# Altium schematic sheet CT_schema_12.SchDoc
size 389 x 385 mm
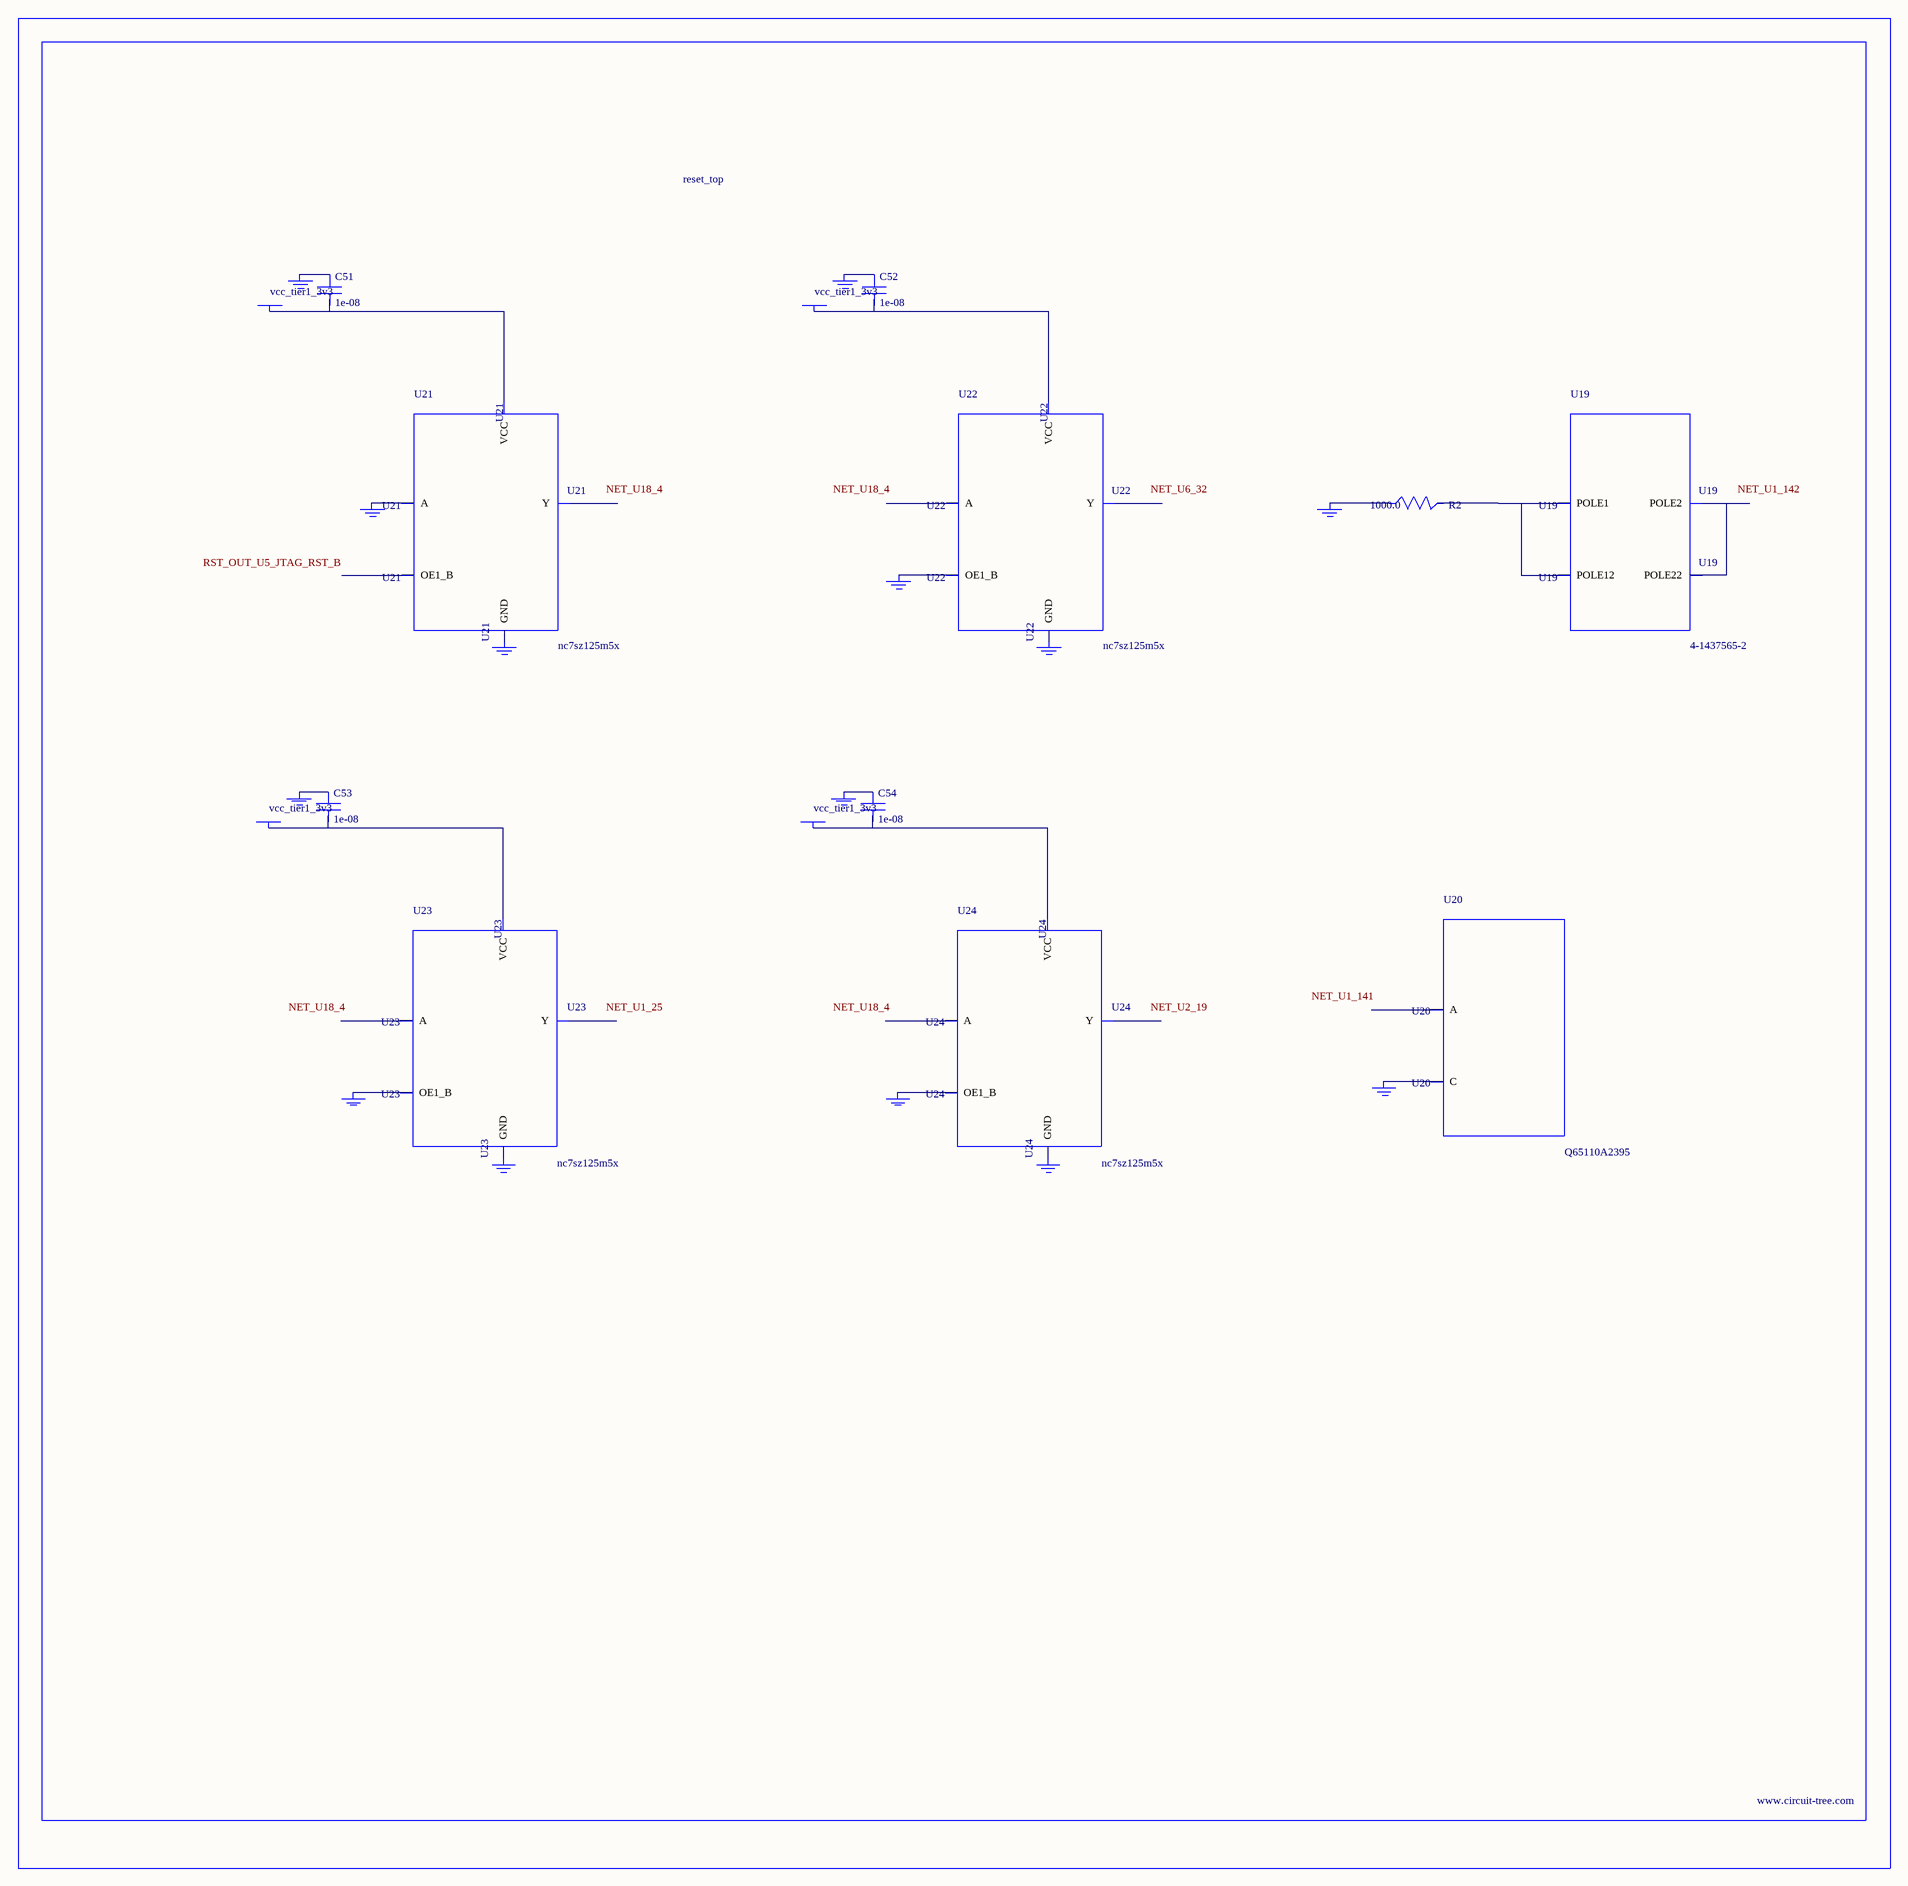
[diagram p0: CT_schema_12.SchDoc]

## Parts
BORDER11  (no value)
C51  1e-08  [C0402]
C52  1e-08  [C0402]
C53  1e-08  [C0402]
C54  1e-08  [C0402]
GND_INSTANCE_11_0  (no value)
GND_INSTANCE_11_1  (no value)
GND_INSTANCE_11_2  (no value)
GND_INSTANCE_11_3  (no value)
GND_INSTANCE_11_4  (no value)
GND_INSTANCE_11_5  (no value)
GND_INSTANCE_11_6  (no value)
GND_INSTANCE_11_7  (no value)
GND_INSTANCE_11_8  (no value)
GND_INSTANCE_11_9  (no value)
GND_INSTANCE_11_10  (no value)
GND_INSTANCE_11_11  (no value)
GND_INSTANCE_11_12  (no value)
GND_INSTANCE_11_13  (no value)
POWER_INSTANCE_11_0  vcc_tier1_3v3
POWER_INSTANCE_11_1  vcc_tier1_3v3
POWER_INSTANCE_11_2  vcc_tier1_3v3
POWER_INSTANCE_11_3  vcc_tier1_3v3
R2  1000.0  [R0603]
U19  4-1437565-2  [SW_4-1437565-2]
U20  Q65110A2395  [LGM67K-G1J2-24-Z]
U21  nc7sz125m5x  [NC7SZ125M5X]
U22  nc7sz125m5x  [NC7SZ125M5X]
U23  nc7sz125m5x  [NC7SZ125M5X]
U24  nc7sz125m5x  [NC7SZ125M5X]

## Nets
NetC51_1: C51.1 GND_INSTANCE_11_2.0(GND)
NetC51_2: C51.2 POWER_INSTANCE_11_0.0(PWR) U21.5(VCC)
NetC52_1: C52.1 GND_INSTANCE_11_5.0(GND)
NetC52_2: C52.2 POWER_INSTANCE_11_1.0(PWR) U22.5(VCC)
NetC53_1: C53.1 GND_INSTANCE_11_8.0(GND)
NetC53_2: C53.2 POWER_INSTANCE_11_2.0(PWR) U23.5(VCC)
NetC54_1: C54.1 GND_INSTANCE_11_11.0(GND)
NetC54_2: C54.2 POWER_INSTANCE_11_3.0(PWR) U24.5(VCC)
NetGND_INSTANCE_11_0_0: GND_INSTANCE_11_0.0(GND) R2.1
NetGND_INSTANCE_11_1_0: GND_INSTANCE_11_1.0(GND) U20.C
NetGND_INSTANCE_11_3_0: GND_INSTANCE_11_3.0(GND) U21.2(A)
NetGND_INSTANCE_11_4_0: GND_INSTANCE_11_4.0(GND) U21.3(GND)
NetGND_INSTANCE_11_6_0: GND_INSTANCE_11_6.0(GND) U22.1(OE1_B)
NetGND_INSTANCE_11_7_0: GND_INSTANCE_11_7.0(GND) U22.3(GND)
NetGND_INSTANCE_11_9_0: GND_INSTANCE_11_9.0(GND) U23.1(OE1_B)
NetGND_INSTANCE_11_10_0: GND_INSTANCE_11_10.0(GND) U23.3(GND)
NetGND_INSTANCE_11_12_0: GND_INSTANCE_11_12.0(GND) U24.1(OE1_B)
NetGND_INSTANCE_11_13_0: GND_INSTANCE_11_13.0(GND) U24.3(GND)
NetR2_2: R2.2 U19.1(POLE1) U19.2(POLE12)
NetU19_3: U19.3(POLE2) U19.4(POLE22)

Not connected (* = marked no-connect by the designer): U20 A; U21 1(OE1_B) 4(Y); U22 2(A) 4(Y); U23 2(A) 4(Y); U24 2(A) 4(Y)

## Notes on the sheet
- Labels drawn without touching a wire or pin: NET_U1_25, NET_U1_141, NET_U1_142, NET_U2_19, NET_U6_32, NET_U18_4, RST_OUT_U5_JTAG_RST_B

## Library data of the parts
BORDER11 = BORDER_PAGE11
C51-C54 = C0402C103K3RAC
GND_INSTANCE_11_0-GND_INSTANCE_11_13 = GND
POWER_INSTANCE_11_0-POWER_INSTANCE_11_3 = PWR
R2 = RC0603JR-071KL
